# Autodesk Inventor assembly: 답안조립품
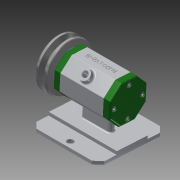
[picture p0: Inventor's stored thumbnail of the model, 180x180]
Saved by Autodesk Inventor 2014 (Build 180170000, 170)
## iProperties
Created: 2018-06
Part Number: 답안조립품
Document SubType Name: Assembly
Designer: geosung1
Author: geosung1
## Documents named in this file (11)
- C:\Users\geosung1\Desktop\480608V1005\답안조립품.iam
- C:\Users\geosung1\Desktop\480608V1005\본체.ipt
- C:\Users\geosung1\Desktop\480608V1005\베어링 15x32x9.ipt
- C:\Users\geosung1\Desktop\480608V1005\축.ipt
- C:\Users\geosung1\Desktop\480608V1005\뒤커버.ipt
- C:\Users\geosung1\Desktop\480608V1005\앞커버.ipt
- C:\Users\geosung1\Desktop\480608V1005\볼트 M4x12.ipt
- C:\Users\geosung1\Desktop\480608V1005\오일 실 15 25 7.ipt
- C:\Users\geosung1\Desktop\480608V1005\V벨트풀리.ipt
- C:\Users\geosung1\Desktop\480608V1005\키 3x3x12.ipt
- 키 3x3x12.ipt
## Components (1 placed, 1 different names)
1. V벨트풀리:1
